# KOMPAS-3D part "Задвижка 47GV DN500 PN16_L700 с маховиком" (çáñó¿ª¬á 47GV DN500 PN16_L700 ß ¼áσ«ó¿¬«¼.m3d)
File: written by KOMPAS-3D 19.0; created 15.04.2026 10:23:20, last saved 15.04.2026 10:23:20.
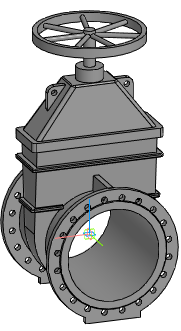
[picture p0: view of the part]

Document properties: Автор: Евгений; Полное имя файла: Z:\3.Личные\kachalov\3d для проектировщиков\2.1 Тип 47GV, 47GV.Z\Задвижка 47GV_DN40-DN600\stp_Задвижка 47GV\Задвижка 47GV DN500 PN16_L700 с маховиком.m3d

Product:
- Part/product: Задвижка 47GV DN500 PN16_L700 с маховиком

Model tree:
1. Операция без истории:1  (labels: Задвижка 47GV DN500 PN16_L700 с маховиком)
